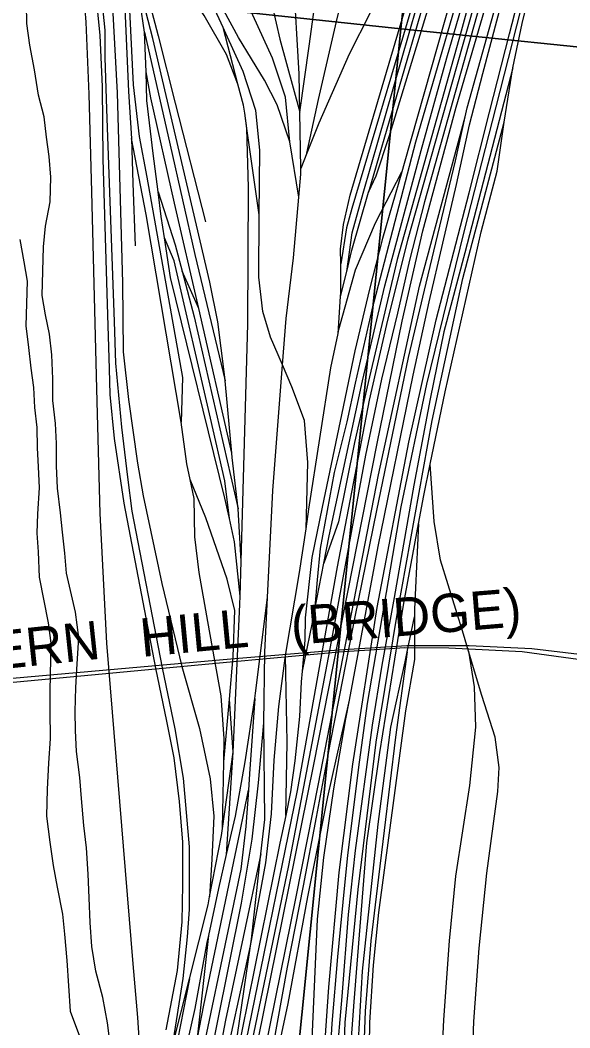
# Model space of a CAD drawing. Extents: x -8.2 to 38.5, y -0.1 to 21.9.
# Drawn here: x 5.4346 to 5.7059, y 15.5938 to 16.091 of the extents above; entities that cross this region are included whole.
import ezdxf

# ---------------------------------------------------------------- set-up
doc = ezdxf.new("R2010")
doc.units = 0
for name, color, linetype in [('GM_X_Adjacent_County_Text', 7, 'Continuous'), ('GM_X_Major_Lake', 7, 'Continuous'), ('GM_X_Minor_River', 7, 'Continuous'), ('GM_X_Township_Text', 7, 'Continuous'), ('GM_X_US_Location', 7, 'Continuous')]:
    doc.layers.add(name, color=color, linetype=linetype)

msp = doc.modelspace()

# ---------------------------------------------------------------- linework, layer by layer
at = {"layer": 'GM_X_Adjacent_County_Text'}
msp.add_lwpolyline([(5.03564, 17.19219), (5.7325, 17.12325), (5.62246, 16.0867), (4.62673, 16.19278), (4.67768, 16.66998)], dxfattribs=at)
for points in [[(5.7325, 17.12325), (6.75364, 16.98553), (6.65001, 15.98141), (5.62246, 16.0867)], [(4.62673, 16.19278), (5.62246, 16.0867), (5.52081, 15.07436), (4.5212, 15.1931)], [(6.65001, 15.98141), (6.53061, 14.97169), (5.52081, 15.07436), (5.62246, 16.0867)]]:
    msp.add_lwpolyline(points, close=True, dxfattribs=at)
at = {"layer": 'GM_X_Minor_River'}
for points in [[(5.46194, 15.7989), (5.45755, 15.81814), (5.45669, 15.82804), (5.45547, 15.83832), (5.45459, 15.84784), (5.45304, 15.86003), (5.45259, 15.87106), (5.45252, 15.88207), (5.45204, 15.89196), (5.45084, 15.90338), (5.45077, 15.91402), (5.45034, 15.9258), (5.44911, 15.93609), (5.4471, 15.94564), (5.44547, 15.95517), (5.44615, 15.97908), (5.44719, 15.9893), (5.44943, 16.00139), (5.44977, 16.01353), (5.44892, 16.02381), (5.44767, 16.03334), (5.44643, 16.04324), (5.4437, 16.05395), (5.44177, 16.06654), (5.43946, 16.07875), (5.43787, 16.08943), (5.43775, 16.09892)], [(5.43449, 15.98281), (5.43646, 15.97175), (5.43809, 15.96221), (5.43747, 15.9402), (5.43869, 15.92954), (5.43992, 15.91925), (5.44117, 15.90973), (5.44165, 15.89984), (5.44288, 15.88993), (5.44299, 15.88005), (5.44348, 15.87055), (5.44395, 15.86028), (5.44321, 15.84739), (5.44294, 15.83791), (5.44358, 15.82861), (5.44404, 15.81607), (5.44852, 15.79354)], [(5.47964, 15.58054), (5.47775, 15.59615), (5.47541, 15.60874), (5.47194, 15.62173), (5.46996, 15.63393), (5.46912, 15.64572), (5.46866, 15.65788), (5.4682, 15.66966), (5.46738, 15.68259), (5.46614, 15.69363), (5.46496, 15.70695), (5.46407, 15.71722), (5.4625, 15.73017), (5.462, 15.74043), (5.46186, 15.74993), (5.46215, 15.76169), (5.46282, 15.77344), (5.46352, 15.78633), (5.46194, 15.7989)], [(5.44852, 15.79354), (5.4498, 15.78364), (5.44921, 15.76012), (5.44934, 15.75024), (5.44938, 15.73657), (5.4487, 15.72444), (5.448, 15.71155), (5.44767, 15.69827), (5.44924, 15.68533), (5.45085, 15.6739), (5.45286, 15.66322), (5.45556, 15.64986), (5.45646, 15.63997), (5.45765, 15.62703), (5.4593, 15.60193), (5.46393, 15.58967)]]:
    msp.add_lwpolyline(points, dxfattribs=at)
at = {"layer": 'GM_X_Township_Text'}
for points in [[(5.35058, 15.75327), (5.36227, 15.75224), (5.39896, 15.75698), (5.41243, 15.76247), (5.41702, 15.7631), (5.53825, 15.77434), (5.5921, 15.77927), (5.62445, 15.78144), (5.64616, 15.78124), (5.68235, 15.77949), (5.73877, 15.77176), (5.74901, 15.77008), (5.82828, 15.75708)], [(5.39447, 15.76297), (5.41217, 15.76468), (5.53864, 15.7759), (5.59173, 15.78026), (5.62535, 15.78248), (5.65622, 15.78248), (5.6871, 15.78092), (5.71063, 15.77811), (5.73505, 15.77479), (5.74946, 15.77294), (5.82847, 15.75936)]]:
    msp.add_lwpolyline(points, dxfattribs=at)
at = {"layer": 'GM_X_US_Location'}
for p, q in [((5.64002, 16.12125), (5.60655, 16.00616)), ((5.5421, 16.05942), (5.53481, 16.08741)), ((5.49674, 16.06554), (5.49607, 16.08507)), ((5.67345, 16.04069), (5.67767, 16.06747)), ((5.5465, 16.0375), (5.54542, 16.04505)), ((5.57307, 16.01782), (5.57261, 16.04564)), ((5.55263, 15.99498), (5.5465, 16.0375)), ((5.57212, 16.00372), (5.56775, 16.03099)), ((5.57609, 16.02535), (5.57307, 16.01782)), ((5.52287, 15.94878), (5.51465, 15.9671)), ((5.59276, 15.95458), (5.59578, 15.96702)), ((5.59148, 15.93634), (5.59276, 15.95458)), ((5.5391, 15.87737), (5.52287, 15.94878)), ((5.5391, 15.87737), (5.53583, 15.91299)), ((5.54368, 15.824), (5.54227, 15.84981)), ((5.5432, 15.80673), (5.54368, 15.824)), ((5.57992, 15.79934), (5.58455, 15.82311)), ((5.57992, 15.79934), (5.5738, 15.76972)), ((5.6256, 15.77931), (5.62929, 15.79661)), ((5.53514, 15.72504), (5.53791, 15.75593)), ((5.53974, 15.7298), (5.53791, 15.75593)), ((5.53447, 15.69211), (5.53974, 15.7298)), ((5.53653, 15.67925), (5.53974, 15.7298)), ((5.53447, 15.69211), (5.53514, 15.72504)), ((5.52209, 15.58882), (5.52766, 15.63929)), ((5.5377, 15.56125), (5.54825, 15.63425)), ((5.50983, 15.58476), (5.51817, 15.61794))]:
    msp.add_line(p, q, dxfattribs=at)
for points in [[(5.45576, 16.62713), (5.46286, 16.6115), (5.47601, 16.58881), (5.4918, 16.56464), (5.52829, 16.50447), (5.60672, 16.37492), (5.6299, 16.33628), (5.63877, 16.31754), (5.64634, 16.30061), (5.65242, 16.28302), (5.65867, 16.25869), (5.66344, 16.23139), (5.66491, 16.20591), (5.66491, 16.18076), (5.659, 16.14278), (5.65045, 16.11319), (5.62414, 16.0203), (5.62295, 16.01615)], [(5.58455, 15.82311), (5.58715, 15.83649), (5.60359, 15.91311), (5.61461, 15.95996), (5.63253, 16.02671), (5.64519, 16.07242), (5.66196, 16.13012), (5.66722, 16.15445), (5.67067, 16.18207), (5.67116, 16.2069), (5.6687, 16.24192), (5.66245, 16.27052), (5.65505, 16.29798), (5.64305, 16.32428), (5.63088, 16.34713), (5.60096, 16.39498), (5.52994, 16.51285), (5.47552, 16.60328), (5.46256, 16.62575)], [(5.47519, 16.60982), (5.5061, 16.55757), (5.55904, 16.47093), (5.61017, 16.3861), (5.64108, 16.33448), (5.65176, 16.31294), (5.65949, 16.29173), (5.66952, 16.25162), (5.67281, 16.2258), (5.67412, 16.20164), (5.6733, 16.1755), (5.66919, 16.15084), (5.66212, 16.1219), (5.65226, 16.08557), (5.62069, 15.97295), (5.60639, 15.91229), (5.59965, 15.88253), (5.59175, 15.8434), (5.58455, 15.82311)], [(5.52895, 15.50275), (5.54901, 15.60074), (5.57153, 15.71089), (5.59126, 15.82121), (5.60704, 15.90357), (5.61559, 15.94089), (5.62612, 15.98314), (5.64519, 16.05071), (5.6613, 16.10776), (5.66705, 16.12683), (5.67034, 16.14048), (5.67346, 16.15725), (5.67511, 16.17007), (5.67675, 16.19095), (5.67675, 16.21249), (5.67478, 16.24027), (5.66968, 16.26691), (5.66163, 16.29617), (5.65226, 16.31886), (5.64091, 16.34056), (5.61296, 16.38741), (5.53323, 16.51943), (5.51991, 16.54245), (5.51185, 16.55856)], [(5.51185, 16.55856), (5.52829, 16.53275), (5.58419, 16.44019), (5.63828, 16.35042), (5.65012, 16.32905), (5.65702, 16.31425), (5.66607, 16.29091), (5.67429, 16.26049), (5.6779, 16.23501), (5.67938, 16.21331), (5.67988, 16.19523), (5.67807, 16.16843), (5.67379, 16.14278), (5.63417, 16.00139), (5.62677, 15.97262), (5.62085, 15.94648), (5.61296, 15.91393), (5.60507, 15.87628), (5.59948, 15.84619), (5.58732, 15.77994), (5.56709, 15.6739), (5.53701, 15.52906)], [(5.54596, 15.55779), (5.5795, 15.72376), (5.61082, 15.88208), (5.62315, 15.9425), (5.63326, 15.98713), (5.64978, 16.04805), (5.66384, 16.09638), (5.67469, 16.13682), (5.68085, 16.1716), (5.68307, 16.20982), (5.67666, 16.26185), (5.66729, 16.29441), (5.65816, 16.31857), (5.64164, 16.35088), (5.5541, 16.49687), (5.51711, 16.55556), (5.51602, 16.557)], [(5.67767, 16.06747), (5.68235, 16.08942), (5.69148, 16.1274), (5.69937, 16.16291), (5.70257, 16.20409), (5.69961, 16.2433), (5.69074, 16.28424), (5.67693, 16.31827), (5.66164, 16.34737), (5.58691, 16.47265), (5.55653, 16.52011), (5.54257, 16.53666)], [(5.65427, 16.04329), (5.65525, 16.04771), (5.67148, 16.10607), (5.67765, 16.12909), (5.68484, 16.16238), (5.68813, 16.2043), (5.6871, 16.22711), (5.6832, 16.25383), (5.67518, 16.28609), (5.65977, 16.32535), (5.64682, 16.3498), (5.60079, 16.42522), (5.56703, 16.49071)], [(5.59711, 15.7555), (5.61132, 15.8312), (5.62858, 15.91586), (5.63647, 15.95203), (5.64995, 16.0099), (5.65636, 16.03933), (5.66294, 16.06465), (5.67806, 16.1217), (5.68612, 16.15162), (5.68826, 16.16527), (5.69122, 16.19124), (5.69056, 16.22478), (5.68349, 16.26835), (5.67889, 16.28643), (5.66721, 16.31685), (5.65538, 16.34069), (5.64025, 16.36567), (5.60972, 16.42131)], [(5.5421, 16.05942), (5.53642, 16.07402), (5.52542, 16.09327), (5.50236, 16.12755), (5.49446, 16.139), (5.48903, 16.14817), (5.48492, 16.15917), (5.47783, 16.18244)], [(5.5928, 15.97081), (5.59274, 15.97805), (5.59422, 15.99021), (5.59751, 16.00468), (5.62612, 16.10168), (5.63318, 16.12585), (5.63709, 16.14706)], [(5.63709, 16.14706), (5.6368, 16.13177), (5.63335, 16.11598), (5.59833, 15.9981), (5.5957, 15.98857), (5.5928, 15.97081)], [(5.48343, 16.14459), (5.4844, 16.13061), (5.48539, 16.11565), (5.48802, 16.05581), (5.48966, 16.03263)], [(5.48343, 16.14459), (5.4867, 16.12979), (5.48785, 16.11286), (5.49048, 16.0591), (5.49344, 16.03362), (5.49722, 16.01356), (5.51481, 15.91475), (5.51416, 15.89256)], [(5.59578, 15.96702), (5.5985, 15.9861), (5.60392, 16.00567), (5.63417, 16.11105), (5.64312, 16.14222)], [(5.48884, 16.13538), (5.49492, 16.11335), (5.50281, 16.08327), (5.5112, 16.05006), (5.52616, 15.99153)], [(5.65982, 16.13423), (5.62973, 16.03082), (5.6082, 15.94813), (5.59998, 15.91196), (5.59586, 15.89272), (5.58962, 15.86773), (5.58271, 15.83025), (5.58123, 15.81479), (5.57992, 15.79934)], [(5.69172, 16.13615), (5.6694, 16.04821), (5.6535, 15.98649), (5.63514, 15.91139), (5.62254, 15.85092), (5.60583, 15.75379), (5.60165, 15.72244), (5.59617, 15.6788), (5.59457, 15.66245), (5.59125, 15.62873), (5.58847, 15.59592), (5.58697, 15.57041)], [(5.53481, 16.08741), (5.52155, 16.11631), (5.51301, 16.13029)], [(5.56775, 16.03099), (5.5615, 16.04923), (5.55526, 16.0614), (5.54243, 16.08244), (5.52797, 16.10924), (5.51924, 16.1296)], [(5.49361, 15.58618), (5.49271, 15.59882), (5.49041, 15.62538), (5.48377, 15.70544), (5.47739, 15.78358), (5.47407, 15.84755), (5.47241, 15.9091), (5.46998, 16.00627), (5.46871, 16.05453), (5.46718, 16.09003), (5.46475, 16.12144)], [(5.46977, 16.12437), (5.47388, 16.08359), (5.47503, 16.05811), (5.47536, 16.02244), (5.47749, 15.95635), (5.47864, 15.91903), (5.47897, 15.90637), (5.48095, 15.8845), (5.48588, 15.85261), (5.50135, 15.77119), (5.50692, 15.74509), (5.51054, 15.727), (5.51317, 15.70546), (5.51481, 15.68541), (5.51481, 15.66453), (5.51448, 15.64611), (5.51218, 15.62211), (5.50659, 15.59285)], [(5.58438, 15.57591), (5.5869, 15.61375), (5.59212, 15.67033), (5.59879, 15.72384), (5.61086, 15.80123), (5.62647, 15.88279), (5.63986, 15.94313), (5.65613, 16.00573), (5.66622, 16.04568), (5.6761, 16.08419), (5.68516, 16.11941)], [(5.60655, 16.00616), (5.61033, 16.01422), (5.61674, 16.03362), (5.63614, 16.09724), (5.63877, 16.11138), (5.64002, 16.12125)], [(5.53583, 15.91299), (5.53553, 15.91623), (5.53224, 15.94221), (5.52829, 15.96177), (5.50018, 16.08195), (5.4919, 16.11384)], [(5.49607, 16.08507), (5.49393, 16.09954), (5.4919, 16.11384)], [(5.57261, 16.04564), (5.57231, 16.06449), (5.56947, 16.11274)], [(5.50983, 15.58476), (5.51514, 15.61817), (5.51728, 15.63872), (5.51827, 15.6522), (5.51827, 15.68311), (5.51531, 15.71697), (5.5112, 15.7413), (5.50495, 15.77146), (5.48999, 15.84866), (5.48785, 15.86543), (5.48473, 15.89009), (5.48177, 15.92182), (5.48127, 15.94237), (5.47749, 16.0471), (5.47667, 16.07258), (5.47651, 16.08606), (5.47486, 16.10365)], [(5.4798, 16.10365), (5.48243, 16.05515), (5.48522, 15.96144), (5.48555, 15.92741), (5.48818, 15.9039), (5.49262, 15.87233), (5.49541, 15.85622), (5.50462, 15.81298), (5.51443, 15.77214), (5.5232, 15.74147), (5.52846, 15.71664), (5.53027, 15.69823), (5.52928, 15.67702), (5.52811, 15.65833)], [(5.57261, 16.04564), (5.57729, 16.07817), (5.58058, 16.10234)], [(5.57609, 16.02535), (5.58189, 16.05186), (5.59077, 16.09034), (5.59364, 16.10253)], [(5.56775, 16.03099), (5.56561, 16.05302), (5.5592, 16.07225), (5.54768, 16.09741)], [(5.55914, 16.09749), (5.56282, 16.08162), (5.57261, 16.04564)], [(5.60738, 16.09463), (5.59702, 16.07422), (5.58205, 16.04019), (5.57609, 16.02535)], [(5.55263, 15.99498), (5.55296, 16.02688), (5.55098, 16.04644), (5.54474, 16.06567), (5.53619, 16.08442), (5.53481, 16.08741)], [(5.49607, 16.08507), (5.50873, 16.02934), (5.5209, 15.97542), (5.53583, 15.91299)], [(5.67767, 16.06747), (5.65399, 15.97623), (5.64363, 15.93726), (5.63698, 15.90422), (5.62884, 15.86155), (5.61922, 15.80607), (5.61305, 15.77278), (5.60837, 15.74318), (5.59998, 15.68128), (5.59653, 15.64972), (5.59333, 15.60928), (5.59061, 15.57697)], [(5.52287, 15.94878), (5.51087, 16.00073), (5.4992, 16.05269), (5.49674, 16.06554)], [(5.50275, 16.00628), (5.50035, 16.02523), (5.49722, 16.05137), (5.49674, 16.06554)], [(5.54542, 16.04505), (5.54481, 16.04914), (5.5421, 16.05942)], [(5.40227, 14.60999), (5.41111, 14.68274), (5.43289, 14.8529), (5.452, 15.00805), (5.46413, 15.10403), (5.46947, 15.14102), (5.49002, 15.24706), (5.51304, 15.36481), (5.5229, 15.41598), (5.54325, 15.52079), (5.55558, 15.58285), (5.57079, 15.65848), (5.58188, 15.71417), (5.60038, 15.80994), (5.61148, 15.86666), (5.63161, 15.95975), (5.65427, 16.04329)], [(5.5465, 16.0375), (5.5465, 16.03772), (5.54542, 16.04505)], [(5.55702, 15.57093), (5.56647, 15.62375), (5.57448, 15.66382), (5.58086, 15.69773), (5.58784, 15.73452), (5.59216, 15.75712), (5.59997, 15.79658), (5.61065, 15.84898), (5.62627, 15.92461), (5.6349, 15.96119), (5.64949, 16.02161), (5.65427, 16.04329)], [(5.54368, 15.824), (5.54696, 15.94102), (5.54738, 16.0084), (5.5465, 16.0375)], [(5.68209, 14.85544), (5.68334, 14.92026), (5.68186, 14.94245), (5.67569, 14.97476), (5.61897, 15.28277), (5.60344, 15.37327), (5.59924, 15.40435), (5.59641, 15.44273), (5.59333, 15.50069), (5.59312, 15.54651), (5.59497, 15.59645), (5.60134, 15.66201), (5.61038, 15.73476), (5.62086, 15.79867), (5.63792, 15.89341), (5.65313, 15.96348), (5.67345, 16.04069)], [(5.63698, 15.8719), (5.64437, 15.90767), (5.66213, 15.98658), (5.67002, 16.01642), (5.67273, 16.03615), (5.67345, 16.04069)], [(5.51416, 15.89256), (5.49689, 15.99515), (5.48966, 16.03263)], [(5.48966, 16.03263), (5.49032, 16.0106), (5.49147, 15.97969)], [(5.57212, 16.00372), (5.57312, 16.01502), (5.57307, 16.01782)], [(5.62295, 16.01615), (5.61346, 15.98331), (5.60704, 15.95832), (5.59981, 15.9279), (5.59258, 15.89321), (5.5837, 15.85063), (5.5786, 15.82581), (5.57531, 15.79605), (5.57515, 15.78504), (5.5738, 15.76972)], [(5.59148, 15.93634), (5.59192, 15.93843), (5.60014, 15.96785), (5.61, 15.99103), (5.62295, 16.01615)], [(5.50591, 15.98357), (5.50429, 15.99416), (5.50275, 16.00628)], [(5.50275, 16.00628), (5.5112, 15.98018), (5.51465, 15.9671)], [(5.56407, 15.92101), (5.56582, 15.94385), (5.56947, 15.97366), (5.57212, 16.00372)], [(5.59578, 15.96702), (5.59833, 15.97755), (5.60655, 16.00616)], [(5.56407, 15.92101), (5.55822, 15.93464), (5.55443, 15.9473), (5.55246, 15.96424), (5.55263, 15.99498)], [(5.53791, 15.84504), (5.53569, 15.85507), (5.50889, 15.96407), (5.50591, 15.98357)], [(5.53791, 15.84504), (5.53569, 15.86362), (5.52862, 15.89453), (5.5107, 15.97229), (5.50591, 15.98357)], [(5.59276, 15.95458), (5.59291, 15.95667), (5.5928, 15.97081)], [(5.51465, 15.9671), (5.52057, 15.94467), (5.54227, 15.84981)], [(5.57571, 15.84005), (5.57712, 15.84965), (5.58797, 15.91952), (5.59148, 15.93634)], [(5.55668, 15.80618), (5.55933, 15.8589), (5.56407, 15.92101)], [(5.57571, 15.84005), (5.57663, 15.87266), (5.57499, 15.89354), (5.56874, 15.91015), (5.56407, 15.92101)], [(5.51857, 15.86436), (5.51695, 15.87201), (5.51416, 15.89256)], [(5.54227, 15.84981), (5.53931, 15.87513), (5.5391, 15.87737)], [(5.63119, 15.84251), (5.63377, 15.85638), (5.63698, 15.8719)], [(5.65582, 15.77969), (5.65333, 15.78798), (5.64203, 15.82456), (5.63895, 15.84367), (5.63698, 15.8719)], [(5.53514, 15.72504), (5.53536, 15.73637), (5.53388, 15.75758), (5.52731, 15.79424), (5.52303, 15.81841), (5.5209, 15.836), (5.52057, 15.85491), (5.51857, 15.86436)], [(5.53791, 15.75593), (5.5398, 15.77698), (5.54063, 15.79967), (5.53684, 15.81512), (5.52632, 15.84537), (5.51857, 15.86436)], [(5.5432, 15.80673), (5.54046, 15.83354), (5.53791, 15.84504)], [(5.56561, 15.77747), (5.57252, 15.81841), (5.57571, 15.84005)], [(5.63592, 15.20588), (5.63303, 15.22087), (5.61552, 15.31754), (5.60566, 15.3787), (5.60097, 15.4184), (5.59727, 15.46205), (5.59579, 15.52198), (5.59629, 15.56439), (5.59949, 15.60656), (5.60566, 15.68498), (5.61207, 15.72962), (5.62391, 15.80335), (5.63119, 15.84251)], [(5.63119, 15.84251), (5.62929, 15.80031), (5.62929, 15.79661)], [(5.53974, 15.7298), (5.54309, 15.80277), (5.5432, 15.80673)], [(5.55045, 15.75631), (5.55084, 15.75887), (5.55668, 15.80618)], [(5.55486, 15.74421), (5.55533, 15.77914), (5.55668, 15.80618)], [(5.62929, 15.79661), (5.62929, 15.77545), (5.62477, 15.75017), (5.61141, 15.65071), (5.60874, 15.62461), (5.60709, 15.59645), (5.60627, 15.55247), (5.60627, 15.48897), (5.60751, 15.45753), (5.61203, 15.40348), (5.61943, 15.3519), (5.62662, 15.31183), (5.6297, 15.29456), (5.63114, 15.2734)], [(5.62638, 15.29426), (5.62477, 15.30135), (5.61943, 15.31984), (5.61532, 15.34347), (5.60504, 15.41602), (5.60093, 15.46226), (5.60011, 15.50459), (5.60114, 15.57898), (5.6036, 15.62173), (5.61121, 15.69427), (5.61758, 15.74216), (5.62456, 15.77442), (5.6256, 15.77931)], [(5.6256, 15.77931), (5.61984, 15.73722), (5.61141, 15.66817), (5.60771, 15.63673), (5.60483, 15.602), (5.60278, 15.54425), (5.6034, 15.48979), (5.60709, 15.42465), (5.61573, 15.35765), (5.62638, 15.29426)], [(5.65582, 15.77969), (5.65868, 15.76209), (5.65929, 15.74216), (5.65642, 15.71338), (5.64943, 15.66858), (5.64635, 15.63673), (5.64347, 15.59768), (5.64121, 15.54939), (5.64141, 15.52165), (5.64183, 15.48527), (5.64326, 15.4602), (5.64676, 15.41807), (5.6482, 15.3967), (5.64779, 15.3704), (5.64429, 15.34532), (5.63772, 15.31409), (5.63545, 15.29128), (5.63566, 15.2699), (5.63673, 15.25402)], [(5.63673, 15.25402), (5.63792, 15.26312), (5.64676, 15.29169), (5.65539, 15.32128), (5.66032, 15.34841), (5.6634, 15.378), (5.6634, 15.40656), (5.65785, 15.46719), (5.65662, 15.50685), (5.65662, 15.54631), (5.65847, 15.59686), (5.66114, 15.63303), (5.66484, 15.67002), (5.67039, 15.7103), (5.67101, 15.72222), (5.66895, 15.73722), (5.66238, 15.75777), (5.65582, 15.77969)], [(5.54825, 15.63425), (5.55591, 15.67521), (5.55871, 15.69938), (5.56002, 15.72585), (5.56233, 15.75232), (5.56561, 15.77747)], [(5.56566, 15.69858), (5.56637, 15.7347), (5.56561, 15.77747)], [(5.5738, 15.76972), (5.57334, 15.76449), (5.57252, 15.74739), (5.57022, 15.72552), (5.56808, 15.71023), (5.56566, 15.69858)], [(5.53653, 15.67925), (5.54097, 15.6982), (5.54566, 15.72508), (5.55045, 15.75631)], [(5.55045, 15.75631), (5.54788, 15.71917), (5.54732, 15.71112)], [(5.56319, 15.58877), (5.56688, 15.60579), (5.57659, 15.65837), (5.5864, 15.7078), (5.59711, 15.7555)], [(5.62916, 15.15111), (5.62628, 15.167), (5.60227, 15.29507), (5.58978, 15.36412), (5.58748, 15.37991), (5.58468, 15.40687), (5.57893, 15.47477), (5.57811, 15.51373), (5.57728, 15.55533), (5.57909, 15.5956), (5.58139, 15.64739), (5.58452, 15.67781), (5.58945, 15.71167), (5.59537, 15.7462), (5.59711, 15.7555)], [(5.38477, 14.70859), (5.39671, 14.80253), (5.42211, 15.00228), (5.43715, 15.12361), (5.44652, 15.18181), (5.45762, 15.24124), (5.47217, 15.31054), (5.51483, 15.51374), (5.52272, 15.54999), (5.53185, 15.59562), (5.54393, 15.65529), (5.54911, 15.68686), (5.55232, 15.71473), (5.55486, 15.74421)], [(5.55344, 15.67964), (5.55533, 15.69653), (5.55486, 15.74421)], [(5.54732, 15.71112), (5.54607, 15.69307), (5.5436, 15.67211), (5.51869, 15.55367)], [(5.52209, 15.58882), (5.52531, 15.6049), (5.54299, 15.68998), (5.54732, 15.71112)], [(5.56566, 15.69858), (5.56282, 15.68491), (5.5377, 15.56125)], [(5.52811, 15.65833), (5.53398, 15.6886), (5.53447, 15.69211)], [(5.55344, 15.67964), (5.54467, 15.63853), (5.53604, 15.59759), (5.52667, 15.54925), (5.48845, 15.37441), (5.46378, 15.25752), (5.45787, 15.22595), (5.45121, 15.18995), (5.44751, 15.16948), (5.43986, 15.11449), (5.4152, 14.91498), (5.40312, 14.81659), (5.39227, 14.72756), (5.3851, 14.67971)], [(5.52766, 15.63929), (5.53259, 15.66245), (5.53653, 15.67925)], [(5.54825, 15.63425), (5.54872, 15.63753), (5.55344, 15.67964)], [(5.51817, 15.61794), (5.52736, 15.65448), (5.52811, 15.65833)], [(5.38571, 14.77361), (5.38487, 14.80179), (5.3866, 14.82102), (5.39498, 14.8844), (5.40855, 14.9902), (5.42753, 15.13742), (5.43617, 15.19019), (5.45022, 15.26122), (5.466, 15.33865), (5.50102, 15.50708), (5.51113, 15.55936), (5.521, 15.60326), (5.52692, 15.63581), (5.52766, 15.63929)], [(5.38555, 14.63961), (5.39299, 14.69619), (5.41105, 14.84978), (5.42604, 14.97025), (5.4456, 15.12232), (5.45185, 15.16901), (5.45645, 15.19745), (5.46188, 15.22376), (5.46681, 15.24349), (5.49097, 15.3612), (5.51975, 15.50259), (5.54825, 15.63425)], [(5.51817, 15.61794), (5.50785, 15.56504), (5.50004, 15.52147), (5.47311, 15.39467), (5.44784, 15.26931), (5.43386, 15.19862), (5.42647, 15.15546), (5.41927, 15.10142), (5.40222, 14.96969), (5.38214, 14.81764)]]:
    msp.add_lwpolyline(points, dxfattribs=at)

# ---------------------------------------------------------------- texts
at = {"layer": 'GM_X_Major_Lake'}
for s, rotation, p in [('(BRIDGE)', 4.6854, (5.56894, 15.78267)), ('HILL', 5.44, (5.49469, 15.77678)), ('WESTERN', 6.0537, (5.34887, 15.76259))]:
    msp.add_text(s, height=0.018939, rotation=rotation, dxfattribs=at).set_placement(p)

doc.saveas('drawing.dxf')
